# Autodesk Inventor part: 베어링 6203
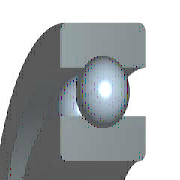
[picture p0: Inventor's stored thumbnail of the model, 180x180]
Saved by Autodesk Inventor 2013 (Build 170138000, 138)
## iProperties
IsCustomPart: 0
Created: 2016-05
Part Number: 베어링 6203
Material: 강철, 연강
Description: 깊은 그루브 볼 베어링
Document SubType Name: Modeling
Standard: KS B 2023
Designer: mduedu
Standards Organization: KS
Language: ko-KR
Size Designation: 6203 - 17 x 40 x 12
Categories: <MemberInstance><Categories><Category DisplayName="샤프트 부품" InternalName="7f7aeb1f-a693-4053-b835-cee3144e0d98" Mnemonic="SHFT"><Category DisplayName="베어링" Inter
Density: 1 g/cm^3
Author: mduedu
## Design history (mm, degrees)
sketch "스케치" dims "d0" = 5.98 (= -0.26 x WD + 0.26 x BD)
  geometry: L1 (3.01, 14.25)-(8.99, 14.25); L2 (6, 14.25)-(6, 11.26); L3 (6, 14.25)-(6, 17.24); L4 (3.778, 12.249)-(0, 12.249); L5 (0, 8.5)-(12, 8.5); L6 (3.778, 16.251)-(0, 16.251); L7 (0, 20)-(12, 20); L8 (12, 8.5)-(12, 12.249); L9 (8.222, 12.249)-(12, 12.249); L10 (8.222, 16.251)-(12, 16.251); L11 (12, 20)-(12, 16.251); L12 (-1.4, 0)-(8.4, 0) reference; L13 (0, -0.3)-(0, 5.3) reference
  constraints: 22 end point, 4 point on line, 2 collinear, 2 perpendicular, 2 symmetric about line, 1 midpoint, 1 parallel, 14 other
  dimensions: "d9" = 17 diameter of L5 L12 (= WD); "d11" = 40 diameter of L7 L12 (= BD); "d12" = 12 distance between parallel lines of L8 L13 (= KB); "d13" = 24.498 diameter of L9 L12 (= 0.326 x BD + 0.674 x WD)
revolve "본체" stored, may be unused: angle "d6" = 90 deg
revolve "볼" stored, may be unused: angle "d7" = 90 deg
pattern_circular "IDS_ARRAYBALL[SIMPL:T]" dims angle "d3" = 360 deg
body "Solid1"
fillet "모깎기1" dims "d1" = 0.6 (= KRS)
other parameters: "WD" = 17 [user parameter; used in 5 equation terms], "BD" = 40 [user parameter; used in 5 equation terms], "KB" = 12 [user parameter; used in 1 equation term], "KRS" = 0.6 [user parameter; used in 1 equation term], "d4" = 0, "d5" = 0, "d8" = 0, "d14" = 0, "d15" = 0, "BBA" = 0 [user parameter], "BC0" = 4750000 [user parameter], "BC" = 9560000 [user parameter], "WR" = 8.5 (= 0.5 x WD) [user parameter]
